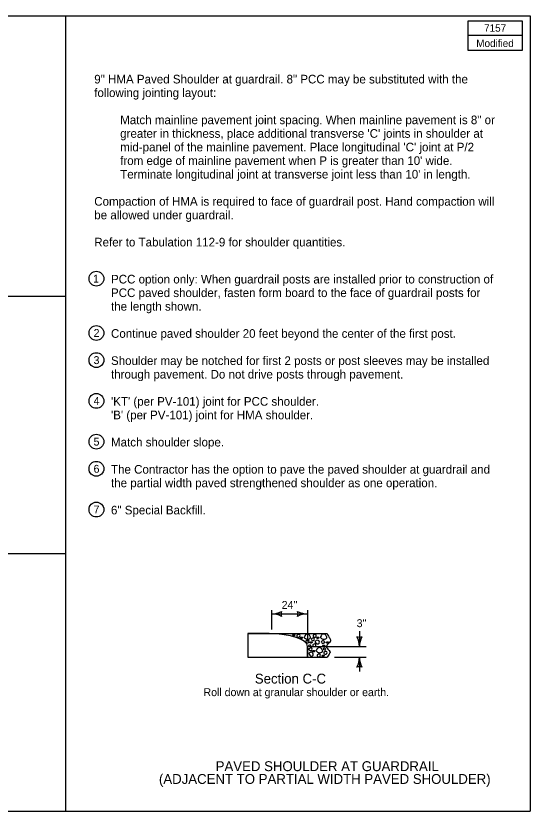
# Model space of a CAD drawing. Extents: x 6410 to 81668, y 3928 to 11667.
# Drawn here: x 8465 to 9506, y 8314 to 9924 of the extents above; entities that cross this region are included whole.
import ezdxf

# ---------------------------------------------------------------- set-up
doc = ezdxf.new("R2010")
doc.units = 0
for name, color, linetype in [('dsnCellElements', 7, 'Continuous'), ('dsnNonPlotable', 7, 'Continuous'), ('dsnShtPlotShapeBatchPrint', 7, 'Continuous'), ('dsnStdBlockModified', 7, 'Continuous'), ('dsnStdNameDate', 7, 'Continuous'), ('dsnStdSection', 7, 'Continuous'), ('Level 11', 7, 'Continuous'), ('Level 3', 7, 'Continuous'), ('Level 7', 7, 'Continuous')]:
    doc.layers.add(name, color=color, linetype=linetype)

msp = doc.modelspace()

# ---------------------------------------------------------------- linework, layer by layer
at = {"layer": 'dsnNonPlotable'}
for p, q in [((6410.4, 9924.4), (9506.1, 9924.4)), ((9506.1, 9924.4), (9506.1, 8314.4)), ((6410.4, 8314.4), (9506.1, 8314.4))]:
    msp.add_line(p, q, dxfattribs=at)
at = {"layer": 'dsnShtPlotShapeBatchPrint'}
for p, q in [((8982.9, 8682.2), (8982.9, 8721.5)), ((8982.9, 8713.6), (9055.4, 8713.6)), ((9055.4, 8721.5), (9055.4, 8658)), ((9160.5, 8678.4), (9160.5, 8647.5)), ((9062.3, 8647.5), (9174.3, 8647.5)), ((9110.2, 8625.7), (9174.3, 8625.7)), ((9160.5, 8625.7), (9160.5, 8597.1))]:
    msp.add_line(p, q, dxfattribs=at)
for centre, radius, start, end in [((8982.9, 8756.1), 42.5, 270, 298.0725), ((8982.9, 8671.1), 42.5, 61.9275, 90), ((9018.5, 8713.6), 16.4, 162.2666, 197.7334), ((9019.8, 8713.6), 16.4, 342.2666, 17.7334), ((9055.4, 8756.1), 42.5, 241.9275, 270), ((9055.4, 8671.1), 42.5, 90, 118.0725), ((9160.5, 8683.1), 16.4, 252.2666, 287.7334), ((9118, 8647.5), 42.5, 0, 28.0725), ((9203, 8647.5), 42.5, 151.9275, 180), ((9118, 8625.7), 42.5, 331.9275, 360), ((9203, 8625.7), 42.5, 180, 208.0725), ((9160.5, 8590), 16.4, 72.2666, 107.7334)]:
    msp.add_arc(centre, radius, start, end, dxfattribs=at)
at = {"layer": 'dsnStdBlockModified'}
for p, q in [((9506.1, 9924.4), (9506.1, 9924.4)), ((8934.5, 8673.7), (8934.5, 8625.7)), ((8934.5, 8673.7), (8977.6, 8673.6)), ((8977.6, 8673.6), (9095.3, 8673.6)), ((9055.4, 8647.5), (9055.4, 8625.7)), ((8934.5, 8625.7), (9055.4, 8625.7)), ((9055.4, 8625.7), (9095.3, 8625.7))]:
    msp.add_line(p, q, dxfattribs=at)
msp.add_ellipse((8977.6, 8647.5), major_axis=(77.9, 0), ratio=0.335273, start_param=0, end_param=1.570796, dxfattribs=at)
msp.add_spline([(9095.3, 8673.6), (9096.7, 8670.4), (9098.6, 8667.3), (9100.4, 8664.2), (9101.9, 8661.1), (9102, 8659.4), (9101.3, 8657.6), (9098.5, 8654.2), (9095.3, 8650.7), (9094.2, 8648.9), (9093.9, 8648), (9093.7, 8647.2), (9093.8, 8646.8), (9094.1, 8645.6), (9095.1, 8644), (9098.1, 8640.8), (9100.5, 8637.6), (9101, 8636), (9100.9, 8635.3), (9100.8, 8634.9), (9100.6, 8634.5), (9095.3, 8625.7)], degree=3, dxfattribs=at)
at = {"layer": 'dsnStdNameDate'}
for points in [[(9027.2, 8669.4), (9028, 8669.2), (9028.6, 8669.2), (9031, 8671.6), (9027, 8672.4), (9023.5, 8670.3), (9026.4, 8669.6), (9027.2, 8669.4)], [(9033.6, 8669.9), (9033.7, 8670.5), (9034, 8670.3), (9038.6, 8673), (9041, 8669.8), (9038.9, 8665.7), (9033.8, 8666.8), (9033.6, 8669.3), (9033.6, 8669.9)], [(9042.8, 8663.9), (9043.7, 8663.7), (9044.2, 8663.7), (9046.6, 8666.1), (9042.6, 8666.9), (9039.1, 8664.8), (9042, 8664.1), (9042.8, 8663.9)], [(9048.5, 8666.1), (9048.2, 8666.6), (9048.8, 8666.3), (9050.7, 8672.7), (9059, 8673), (9061.6, 8665.7), (9061.9, 8664.9), (9057.1, 8661.2), (9050.4, 8663.3), (9048.8, 8665.7), (9048.5, 8666.1)], [(9063, 8662.7), (9063.1, 8663.3), (9063.4, 8663.1), (9068, 8665.8), (9070.4, 8662.6), (9068.2, 8658.6), (9063.2, 8659.7), (9063, 8662.2), (9063, 8662.7)], [(9066.6, 8669.9), (9066.6, 8670.5), (9067, 8670.3), (9071.5, 8673), (9073.9, 8669.8), (9071.8, 8665.7), (9066.7, 8666.8), (9066.5, 8669.3), (9066.6, 8669.9)], [(9075.8, 8663.9), (9076.6, 8663.7), (9077.1, 8663.7), (9079.6, 8666.1), (9075.5, 8666.9), (9072.1, 8664.8), (9074.9, 8664.1), (9075.8, 8663.9)], [(9081.4, 8666.1), (9081.2, 8666.6), (9081.7, 8666.3), (9083.6, 8672.7), (9091.9, 8673), (9094.6, 8665.7), (9094.8, 8664.9), (9090, 8661.2), (9083.3, 8663.3), (9081.7, 8665.7), (9081.4, 8666.1)], [(9052, 8658.7), (9052.1, 8659.2), (9052.4, 8659.1), (9057, 8661.7), (9059.4, 8658.5), (9057.2, 8654.5), (9052.1, 8655.6), (9052, 8658.1), (9052, 8658.7)], [(9057.4, 8649), (9057, 8649.5), (9057.3, 8649.8), (9061.6, 8651.2), (9063, 8647.7), (9059.8, 8646.9), (9057.8, 8648.5), (9057.4, 8649)], [(9062.1, 8654.7), (9063, 8654.5), (9063.5, 8654.5), (9065.9, 8656.9), (9061.9, 8657.7), (9058.4, 8655.6), (9061.3, 8654.8), (9062.1, 8654.7)], [(9065.9, 8650.9), (9065.9, 8651.5), (9066.3, 8651.3), (9070.9, 8654), (9073.3, 8650.8), (9071.1, 8646.8), (9066, 8647.8), (9065.9, 8650.3), (9065.9, 8650.9)], [(9071.1, 8656.7), (9070.5, 8657.9), (9070.7, 8658.2), (9075.3, 8661.2), (9079.3, 8659.3), (9080.4, 8654), (9074.2, 8651.3), (9071.7, 8655.6), (9071.1, 8656.7)], [(9073, 8639), (9072.8, 8639.5), (9073.3, 8639.2), (9075.2, 8645.6), (9083.5, 8645.8), (9086.1, 8638.6), (9086.4, 8637.8), (9081.6, 8634.1), (9074.9, 8636.2), (9073.3, 8638.5), (9073, 8639)], [(9083.3, 8657.3), (9083.4, 8657.9), (9083.7, 8657.7), (9088.3, 8660.4), (9090.7, 8657.2), (9088.5, 8653.2), (9083.4, 8654.3), (9083.3, 8656.8), (9083.3, 8657.3)], [(9086, 8648.6), (9085.6, 8649), (9086, 8649.4), (9090.3, 8650.7), (9091.6, 8647.3), (9088.4, 8646.5), (9086.4, 8648.1), (9086, 8648.6)], [(9095.1, 8654.7), (9095.9, 8654.5), (9096.4, 8654.5), (9098.8, 8656.9), (9094.8, 8657.7), (9091.3, 8655.6), (9094.2, 8654.8), (9095.1, 8654.7)], [(9058.6, 8632.2), (9058, 8633.4), (9058.2, 8633.7), (9062.7, 8636.7), (9066.7, 8634.8), (9067.8, 8629.4), (9061.6, 8626.8), (9059.1, 8631), (9058.6, 8632.2)], [(9058.2, 8642.8), (9058.2, 8643.3), (9058.6, 8643.2), (9063.1, 8645.8), (9065.5, 8642.6), (9063.4, 8638.6), (9058.3, 8639.7), (9058.1, 8642.2), (9058.2, 8642.8)], [(9067.3, 8636.8), (9068.2, 8636.6), (9068.7, 8636.6), (9071.1, 8639), (9067.1, 8639.8), (9063.6, 8637.7), (9066.5, 8637), (9067.3, 8636.8)], [(9074.9, 8630.2), (9074.9, 8630.8), (9075.3, 8630.6), (9079.8, 8633.3), (9082.3, 8630.1), (9080.1, 8626.1), (9075, 8627.1), (9074.8, 8629.6), (9074.9, 8630.2)], [(9086.6, 8627.5), (9087.5, 8627.4), (9088, 8627.4), (9090.4, 8629.8), (9086.4, 8630.6), (9082.9, 8628.4), (9085.8, 8627.7), (9086.6, 8627.5)], [(9087.3, 8642.5), (9086.9, 8643), (9087.3, 8643.3), (9091.6, 8644.7), (9092.9, 8641.2), (9089.7, 8640.4), (9087.7, 8642), (9087.3, 8642.5)], [(9088.5, 8635.6), (9088.5, 8636.2), (9088.9, 8636), (9093.4, 8638.7), (9095.8, 8635.5), (9093.7, 8631.5), (9088.6, 8632.6), (9088.4, 8635.1), (9088.5, 8635.6)]]:
    msp.add_open_spline(points, degree=3, dxfattribs=at)
at = {"layer": 'dsnStdSection'}
msp.add_lwpolyline([(9490.4, 9914.4), (9490.4, 9854.4), (9380.4, 9854.4), (9380.4, 9914.4), (9490.4, 9914.4), (9490.4, 9884.4), (9380.4, 9884.4)], dxfattribs=at)
at = {"layer": 'Level 11'}
for p, q in [((8566, 8314.4), (8566, 9924.4)), ((8566, 9356.4), (6410.4, 9356.4)), ((8566, 8835.4), (6410.4, 8835.4))]:
    msp.add_line(p, q, dxfattribs=at)
at = {"layer": 'Level 3'}
for p, q in [((8977.6, 8673.7), (8934.5, 8673.7)), ((8934.5, 8673.7), (8934.5, 8625.7)), ((9055.4, 8625.7), (9055.4, 8647.5)), ((8934.5, 8625.7), (9055.4, 8625.7))]:
    msp.add_line(p, q, dxfattribs=at)
msp.add_lwpolyline([(8977.6, 8673.6), (8977.6, 8673.7)], dxfattribs=at)
msp.add_ellipse((8977.6, 8647.5), major_axis=(77.9, 0), ratio=0.335273, start_param=0, end_param=1.570796, dxfattribs=at)
at = {"layer": 'Level 7'}
for centre in [(8627.9, 9392.4), (8627.9, 9282.4), (8627.9, 9227.4), (8627.9, 9144.9), (8627.9, 9062.4), (8627.9, 9007.4), (8627.9, 8924.9)]:
    msp.add_circle(centre, 15, dxfattribs=at)

# ---------------------------------------------------------------- texts
at = {"layer": 'dsnCellElements'}
for s, height, p in [('Section C-C', 20, (8948.7, 8572.6)), ('Roll down at granular shoulder or earth.', 16, (8844.8, 8547.1)), ('PAVED SHOULDER AT GUARDRAIL', 20, (8869.4, 8395.3)), ('(ADJACENT TO PARTIAL WIDTH PAVED SHOULDER)', 20, (8754.5, 8369.4))]:
    msp.add_text(s, height=height, dxfattribs=at).set_placement(p)
at = {"layer": 'dsnShtPlotShapeBatchPrint'}
for s, p in [("24''", (9003, 8723.8)), ("3'' ", (9154.9, 8686.8))]:
    msp.add_text(s, height=16, dxfattribs=at).set_placement(p)
at = {"layer": 'dsnStdSection'}
for s, p in [('7157', (9413, 9892.4)), ('Modified', (9397.2, 9861.4))]:
    msp.add_text(s, height=15, dxfattribs=at).set_placement(p)
at = {"layer": 'Level 7'}
for s, height, p in [('9" HMA Paved Shoulder at guardrail. 8" PCC may be substituted with the', 17.5, (8623.5, 9787.6)), ('following jointing layout:', 17.5, (8623.5, 9760.1)), ('Match mainline pavement joint spacing. When mainline pavement is 8" or ', 17.5, (8676, 9705.1)), ("greater in thickness, place additional transverse 'C' joints in shoulder at ", 17.5, (8676, 9677.6)), ("mid-panel of the mainline pavement. Place longitudinal 'C' joint at P/2 ", 17.5, (8676, 9650.1)), ("from edge of mainline pavement when P is greater than 10' wide. ", 17.5, (8676, 9622.6)), ("Terminate longitudinal joint at transverse joint less than 10' in length.", 17.5, (8676, 9595.1)), ('Compaction of HMA is required to face of guardrail post. Hand compaction will ', 17.5, (8623.5, 9540.1)), ('be allowed under guardrail. ', 17.5, (8623.5, 9512.6)), ('Refer to Tabulation 112-9 for shoulder quantities.', 17.5, (8623.5, 9457.6)), ('1', 16, (8621.1, 9384.4)), ('PCC option only: When guardrail posts are installed prior to construction of ', 17.5, (8657.4, 9382.6)), ('PCC paved shoulder, fasten form board to the face of guardrail posts for ', 17.5, (8657.4, 9355.1)), ('the length shown.', 17.5, (8657.4, 9327.6)), ('2', 16, (8622.2, 9274.4)), ('Continue paved shoulder 20 feet beyond the center of the first post.', 17.5, (8657.4, 9272.6)), ('3', 16, (8622.1, 9219.4)), ('Shoulder may be notched for first 2 posts or post sleeves may be installed ', 17.5, (8657.4, 9217.6)), ('through pavement. Do not drive posts through pavement.', 17.5, (8657.4, 9190.1)), ('4', 16, (8622.2, 9136.9)), ("'KT' (per PV-101) joint for PCC shoulder.", 17.5, (8657.4, 9135.1)), ("'B' (per PV-101) joint for HMA shoulder.", 17.5, (8657.4, 9107.6)), ('5', 16, (8622.1, 9054.4)), ('Match shoulder slope.', 17.5, (8657.4, 9052.6)), ('6', 16, (8622.1, 8999.4)), ('The Contractor has the option to pave the paved shoulder at guardrail and ', 17.5, (8657.4, 8997.6)), ('the partial width paved strengthened shoulder as one operation.', 17.5, (8657.4, 8970.1)), ('7', 16, (8622.1, 8916.9)), ('6" Special Backfill.', 17.5, (8657.4, 8915.1))]:
    msp.add_text(s, height=height, dxfattribs=at).set_placement(p)

doc.saveas('drawing.dxf')
